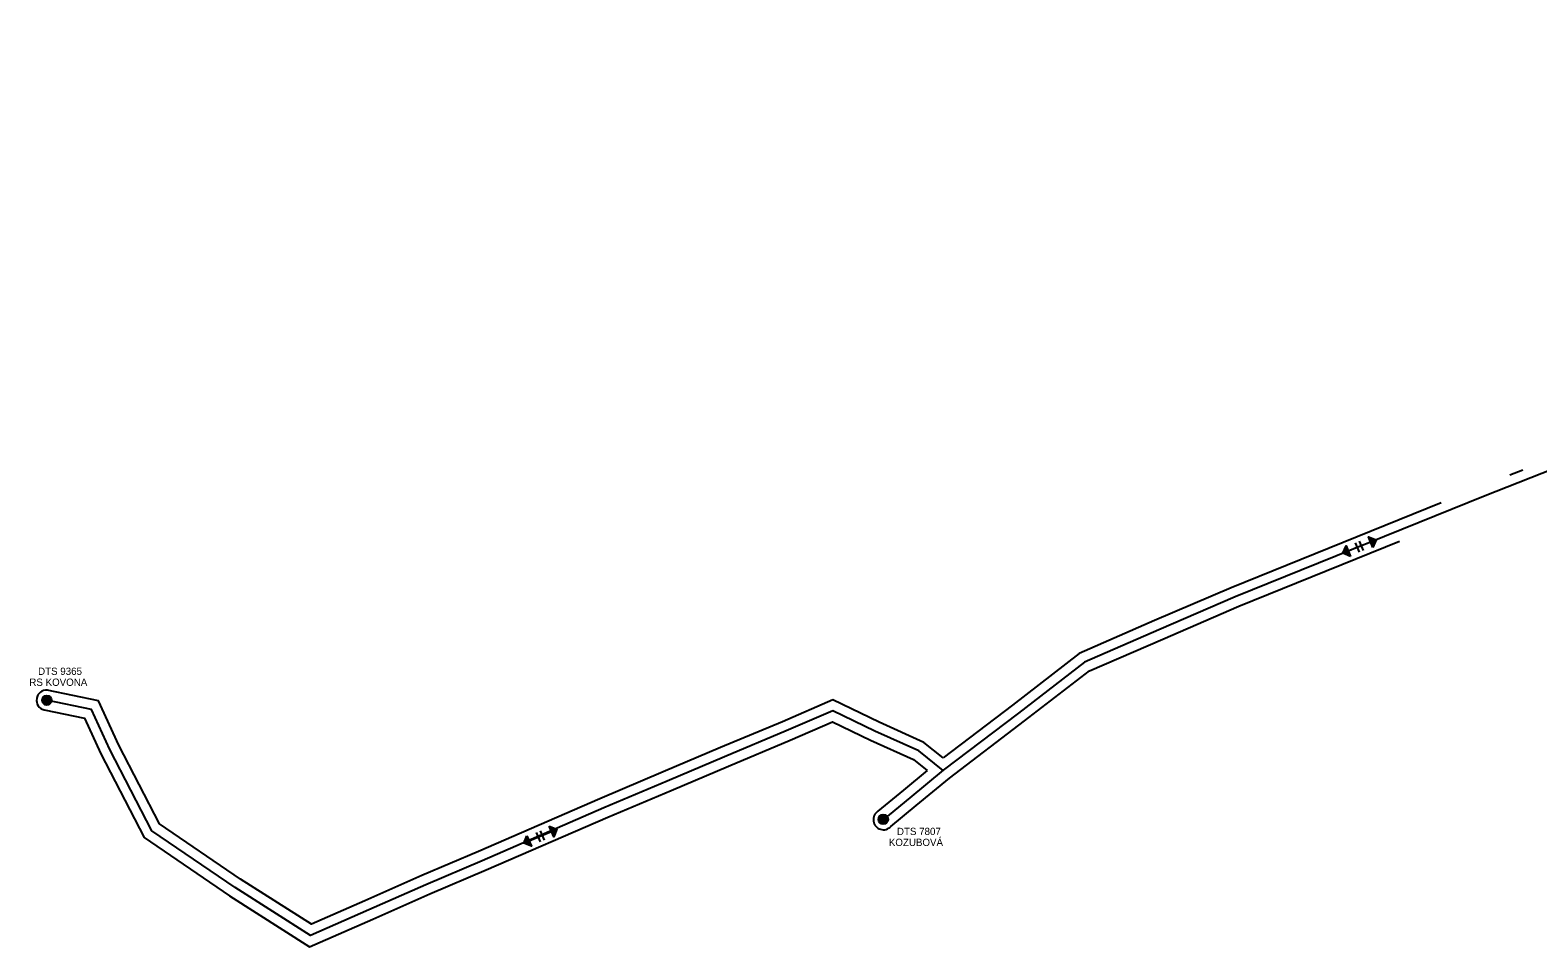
# Model space of a CAD drawing. Extents: x -444817 to -434929, y -1145681 to -1129851.
# Drawn here: x -444817 to -443163, y -1134006 to -1133000 of the extents above; entities that cross this region are included whole.
import ezdxf

# ---------------------------------------------------------------- set-up
doc = ezdxf.new("R2010")
doc.units = 0
for name, color, linetype in [('Vrstva 10', 7, 'Continuous'), ('Vrstva 11', 7, 'Continuous'), ('Vrstva 13', 7, 'Continuous'), ('Vrstva 15', 7, 'Continuous')]:
    doc.layers.add(name, color=color, linetype=linetype)

msp = doc.modelspace()

# ---------------------------------------------------------------- linework, layer by layer
at = {"layer": 'Vrstva 10'}
for p, q in [((-443360.7, -1133567.6), (-443362.8, -1133562.4)), ((-443358.6, -1133572.8), (-443360.7, -1133567.6)), ((-443356.3, -1133565.8), (-443358.4, -1133560.6)), ((-443354.2, -1133571), (-443356.3, -1133565.8)), ((-444261.9, -1133880.1), (-444259.7, -1133885.3)), ((-444257.5, -1133878.2), (-444255.3, -1133883.4)), ((-444259.7, -1133885.3), (-444257.5, -1133890.4)), ((-444255.3, -1133883.4), (-444253.1, -1133888.6))]:
    msp.add_line(p, q, dxfattribs=at)
for points in [[(-442655.5, -1133000.4), (-442743.1, -1133037.4), (-442861.3, -1133223.2), (-442916.9, -1133291.7), (-442985.2, -1133371.5), (-443039.7, -1133433.2), (-443134.2, -1133477.2), (-443220.6, -1133510.9), (-443495.1, -1133621.9), (-443578.9, -1133658), (-443660.4, -1133693.4), (-443732.6, -1133749.2), (-443815.3, -1133812), (-443852, -1133842.2), (-443880.9, -1133866.1)], [(-443346.2, -1133561.7), (-443358.5, -1133566.7), (-443370.9, -1133571.7)], [(-443815.4, -1133812.1), (-443842.2, -1133790.8), (-443890.4, -1133769.1), (-443936.6, -1133746.8), (-443987.5, -1133768.8), (-444055.4, -1133797.2), (-444118.2, -1133824), (-444187.7, -1133853.3), (-444321.1, -1133911.2), (-444383, -1133937.5), (-444445.6, -1133965), (-444509.7, -1133993.1), (-444592.3, -1133940.6), (-444683.8, -1133878.3), (-444729.9, -1133789.1), (-444750, -1133745.3), (-444799.2, -1133735.1)], [(-444269.8, -1133889.5), (-444257.5, -1133884.3), (-444245.2, -1133879.2)]]:
    msp.add_lwpolyline(points, dxfattribs=at)
for points in [[(-443368.5, -1133577.5), (-443376.7, -1133574), (-443373.2, -1133565.8)], [(-443369.8, -1133576.2), (-443375.8, -1133573.7), (-443373.3, -1133567.7)], [(-443343.9, -1133567.5), (-443348.6, -1133555.9), (-443340.4, -1133559.3)], [(-443343.8, -1133565.7), (-443347.3, -1133557.2), (-443341.3, -1133559.7)], [(-443343.8, -1133563.9), (-443346, -1133558.5), (-443342.2, -1133560.1)], [(-443343.8, -1133562), (-443344.7, -1133559.8), (-443343.1, -1133560.4)], [(-443371.1, -1133574.9), (-443374.9, -1133573.3), (-443373.3, -1133569.5)], [(-443372.4, -1133573.6), (-443374, -1133572.9), (-443373.3, -1133571.3)], [(-444247.7, -1133873.4), (-444239.4, -1133876.7), (-444242.8, -1133885)], [(-444246.4, -1133874.6), (-444240.4, -1133877.1), (-444242.8, -1133883.1)], [(-444245.1, -1133875.9), (-444241.3, -1133877.5), (-444242.8, -1133881.3)], [(-444243.8, -1133877.2), (-444242.2, -1133877.9), (-444242.8, -1133879.5)], [(-444272.2, -1133883.7), (-444267.3, -1133895.3), (-444275.6, -1133892)], [(-444272.2, -1133885.5), (-444268.6, -1133894), (-444274.6, -1133891.6)], [(-444272.2, -1133887.4), (-444269.9, -1133892.7), (-444273.7, -1133891.2)], [(-444272.2, -1133889.2), (-444271.2, -1133891.5), (-444272.8, -1133890.8)]]:
    msp.add_lwpolyline(points, close=True, dxfattribs=at)
at = {"layer": 'Vrstva 11'}
for centre, radius in [((-444799, -1133735.2), 5.25), ((-444799, -1133735.2), 4.55), ((-444799, -1133735.2), 3.85), ((-444799, -1133735.2), 3.15), ((-444799, -1133735.2), 2.45), ((-444799, -1133735.2), 1.75), ((-444799, -1133735.2), 1.05), ((-444799, -1133735.2), 0.35), ((-443881.1, -1133865.8), 5.25), ((-443881.1, -1133865.8), 4.55), ((-443881.1, -1133865.8), 3.85), ((-443881.1, -1133865.8), 3.15), ((-443881.1, -1133865.8), 2.45), ((-443881.1, -1133865.8), 1.75), ((-443881.1, -1133865.8), 1.05), ((-443881.1, -1133865.8), 0.35)]:
    msp.add_circle(centre, radius, dxfattribs=at)
at = {"layer": 'Vrstva 15'}
for points in [[(-443179.4, -1133483), (-443193.5, -1133488.5)], [(-443269, -1133518.6), (-443499.4, -1133611.8), (-443583.3, -1133647.9), (-443666, -1133683.9), (-443739.3, -1133740.4), (-443815.3, -1133798.2)], [(-443872.8, -1133873.6), (-443845, -1133850.7), (-443808.4, -1133820.6), (-443726, -1133757.9), (-443654.7, -1133703), (-443574.5, -1133668.1), (-443490.9, -1133632.1), (-443314.5, -1133560.7)], [(-443815.3, -1133798.2), (-443836.5, -1133781.4), (-443885.7, -1133759.2), (-443936.3, -1133734.7), (-443991.8, -1133758.7), (-444059.7, -1133787.1), (-444122.5, -1133813.8), (-444192, -1133843.2), (-444325.4, -1133901.1), (-444387.4, -1133927.4), (-444450, -1133955), (-444508.7, -1133980.7), (-444586.3, -1133931.4), (-444675.3, -1133870.8), (-444720, -1133784.3), (-444742.3, -1133735.7), (-444798.5, -1133724)], [(-444802.1, -1133745.8), (-444757.7, -1133754.9), (-444739.8, -1133793.9), (-444692.3, -1133885.8), (-444598.4, -1133949.8), (-444510.6, -1134005.6), (-444441.2, -1133975.1), (-444378.7, -1133947.6), (-444316.8, -1133921.3), (-444183.3, -1133863.4), (-444113.9, -1133834.1), (-444051.1, -1133807.3), (-443983.2, -1133778.9), (-443936.9, -1133758.9), (-443895, -1133779.1), (-443848, -1133800.3), (-443832.9, -1133812.3)], [(-443832.9, -1133812.3), (-443859, -1133833.7), (-443887, -1133856.8)]]:
    msp.add_lwpolyline(points, dxfattribs=at)
for centre, start, end in [((-444799.2, -1133735.1), 85.967, 255.278), ((-443880.9, -1133866.1), 123.2072, 317.2524)]:
    msp.add_arc(centre, 11.1, start, end, dxfattribs=at)

# ---------------------------------------------------------------- texts
at = {"layer": 'Vrstva 13'}
for s, p in [('DTS 9365', (-444808.6, -1133707.4)), ('RS KOVONA', (-444818.2, -1133719.4)), ('DTS 7807', (-443866.1, -1133883)), ('KOZUBOVÁ', (-443875, -1133895))]:
    msp.add_text(s, height=8, dxfattribs=at).set_placement(p)

doc.saveas('drawing.dxf')
